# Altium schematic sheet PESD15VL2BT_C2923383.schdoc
size 127 x 101 mm
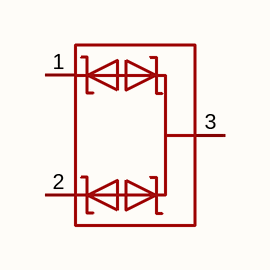
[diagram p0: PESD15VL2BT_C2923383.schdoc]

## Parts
U?  pesd15vl2bt_c2923383  [SOT-23-3_L2.9-W1.3-P1.90-LS2.4-BR]  (value not drawn)

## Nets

Not connected (* = marked no-connect by the designer): U? 1(C1) 2(C2) 3(A)

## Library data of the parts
U? = pesd15vl2bt_c2923383: 极性:双向;反向截止电压(Vrwm):15V;钳位电压:38V;峰值脉冲电流(Ipp):5A;峰值脉冲功率(Ppp):150W;击穿电压:16.5V;; Manufacturer: TECH PUBLIC(台舟); AddInBom: yes; ModelId: c62791f0466c4ae2a892c056b845b0ca; ModelName: SOT-23-3P_L2.9-W1.3-H1.0-LS2.4-P0.95; ModelTransform: 98.425,114.173,0,180,0,0,0.0005,-0.0005,0; Polarity: 双向; Reverse Stand-Off Voltage (Vrwm): 15V; Clamping Voltage: 38V; Peak Pulse Current (Ipp): 5A; Peak Pulse Power Dissipation (Ppp): 150W; Voltage - Breakdown: 16.5V; Reverse Leakage Current (Ir): 100nA; Number of Channels: 双路; level of protection: IEC 61000-4-2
